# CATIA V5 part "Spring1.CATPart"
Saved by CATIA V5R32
Part number: Part1
Bounding box of the stored display mesh (mm): x -50 to 50, y -44.999 to 44.983, z -4.984 to 154.984
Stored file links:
  D:\PROJECTS\Project 2022\CATIA V5 6R 2022\Resources\Tutorial Files\c19_catia_v5_6r2022_tut\C19_tut_01.CATPart\Spring1.CATPart
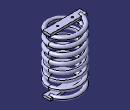
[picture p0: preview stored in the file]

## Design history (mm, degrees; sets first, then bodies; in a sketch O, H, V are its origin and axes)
Body1 (main body)
  Point1: (0, 0, 0)
  Point2: (0, 0, 150)
  Line1: type PtPt, FirstPoint Point2, SecondPoint Point1
  Point3: (40, 0, 0)
  Helix1: Direction Line1, RefPoint Point3, Pitch 20, Height 150, TaperAngle 0, Revolutions 1
  Plane1: type Normal, Curve Helix1, RefPoint vertex of Helix1, Ratio 0
  Sketch1 on Plane1, origin (0, -11.8615, 0.9439), H (1, 0, 0), V (0, 0.0793, 0.9968)
    circle A1 centre (-40, 149.5273) radius 5
    point P1 (-40, 149.5273)
    reference projected point E1 (-40, 149.5273) from vertex of Helix1
    radius A1 = 5
    coincidence: P1 E1
  Rib1: profile Sketch1, centre curve Helix1
  Sketch2 on xy-plane, origin (0, 0, 0), H (1, 0, 0), V (0, 1, 0)
    line L1 (-50, 10) -> (50, 10)
    line L2 (50, 10) -> (50, -10)
    line L3 (50, -10) -> (-50, -10)
    line L4 (-50, -10) -> (-50, 10)
    length L1 = 100
    distance L1 L3 = 20
    horizontal: L1 H, L3 H
    vertical: L2 V, L4 V
    symmetry: L3 L1 H, L2 L4 V
  Pad1: profile Sketch2, direction (0, 0, 1), length 3, mirrored extent
  Sketch3 on start face of Pad1, origin (0, 0, -3), H (1, 0, 0), V (0, -1, 0)
    circle A1 centre (-24.223, 0) radius 2.5
    point P1 (-24.223, 0)
    circle A2 centre (24.223, 0) radius 2.5
    point P2 (24.223, 0)
    radius A2 = 2.5
    coincidence: P1 H, P2 H
    symmetry: A2 A1 V
  Pocket1: profile Sketch3, direction (0, 0, 1), length 3
  Plane2: type Offset, RefPlane xy-plane, Offset 150
  Sketch4 on Plane2, origin (0, 0, 150), H (1, 0, 0), V (0, 1, 0)
    line L1 (-50, 10) -> (50, 10)
    line L2 (50, 10) -> (50, -10)
    line L3 (50, -10) -> (-50, -10)
    line L4 (-50, -10) -> (-50, 10)
    reference projected line E1 (50, -10) -> (50, 10) from edge [face of Pad1 from Sketch2.L2 | end face of Pad1]
    reference projected line E2 (-50, 10) -> (-50, -10) from edge [face of Pad1 from Sketch2.L4 | end face of Pad1]
    reference projected line E3 (-50, -10) -> (50, -10) from edge [face of Pad1 from Sketch2.L3 | end face of Pad1]
    reference projected line E4 (50, 10) -> (-50, 10) from edge [face of Pad1 from Sketch2.L1 | end face of Pad1]
    horizontal: L1 H, L3 H
    vertical: L2 V, L4 V
    coincidence: L2 E1, L4 E2, E3 L3, L1 E4
  Pad2: profile Sketch4, direction (0, 0, 1), length 3, mirrored extent
  Sketch5 on end face of Pad2, origin (0, 0, 153), H (1, 0, 0), V (0, 1, 0)
    circle A1 centre (-20.0406, 0) radius 2.5674
    point P1 (-20.0406, 0)
    circle A2 centre (20.0406, 0) radius 2.5674
    coincidence: P1 H
    symmetry: A1 A2 V
  Pocket2: profile Sketch5, direction (0, 0, -1), through (limit type 6)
